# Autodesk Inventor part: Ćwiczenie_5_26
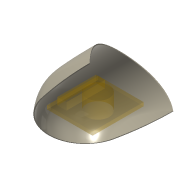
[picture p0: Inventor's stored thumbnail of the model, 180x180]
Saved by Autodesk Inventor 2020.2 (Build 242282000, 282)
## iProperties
Created: 2005-03
Part Number: Ćwiczenie_5_26
Document SubType Name: Modeling
Designer: F.Stasiak
Manufacturer: Standard
Standards Organization: Custom
Density: 1 g/cm^3
Material: Ogólny
Appearance: Jasnobeżowa
Manager: www.cadconsulting.pl
Company: Fabian Stasiak CAD Consulting
Standard konwersji: STEP AP214DIS
Nazwa pliku: C:\\Ćwiczenia\\Żebro\\Modelik.stp
Preprocesor: Autodesk Inventor 9
Postprocesor: Build: 147, Release: 9 SP2 - Date: Thu 12/16/2004
Przesłane jednostki: MILLIMETERS
Niepewność: 0.01
Author: F.Stasiak
Subject: Zbiór ćwiczeń. Autodesk Inventor 2020. Kurs podstawowy
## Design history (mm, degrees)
feature "Baza1"
feature "Komponenty"
node "Bryła1"
node "Korpusy bryłowe"
node "Korpusy powierzchniowe"
body "Srf1"
